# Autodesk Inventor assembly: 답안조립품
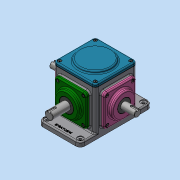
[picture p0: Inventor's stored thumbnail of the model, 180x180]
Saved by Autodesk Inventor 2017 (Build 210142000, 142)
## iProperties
Part Number: 답안조립품
Material: 일반
Document SubType Name: Assembly
Designer: MRC
Mass: 3235.88 g
Surface Area: 2651.66 cm^2
Volume: 866.536 cm^3
Density: 3.73427 g/cm^3
Author: MRC
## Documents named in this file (16)
- C:\Users\MRC\Desktop\620307V1002\답안조립품.iam
- C:\Users\MRC\Desktop\620307V1002\본체.ipt
- C:\Users\MRC\Desktop\620307V1002\개스킷.ipt
- C:\Users\MRC\Desktop\620307V1002\메인베벨기어.ipt
- C:\Users\MRC\Desktop\620307V1002\메인축.ipt
- C:\Users\MRC\Desktop\620307V1002\메인커버.ipt
- C:\Users\MRC\Desktop\620307V1002\베어링 6203.ipt
- C:\Users\MRC\Desktop\620307V1002\베어링 6204.ipt
- C:\Users\MRC\Desktop\620307V1002\볼트 M4.ipt
- C:\Users\MRC\Desktop\620307V1002\상부커버.ipt
- C:\Users\MRC\Desktop\620307V1002\서브베벨기어.ipt
- C:\Users\MRC\Desktop\620307V1002\서브축.ipt
- C:\Users\MRC\Desktop\620307V1002\서브커버.ipt
- C:\Users\MRC\Desktop\620307V1002\오일 실 17 32 8.ipt
- C:\Users\MRC\Desktop\620307V1002\오일 실 20 35 8.ipt
- C:\Users\MRC\Desktop\620307V1002\키 4x4.ipt
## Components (1 placed, 1 different names)
1. 개스킷:1
